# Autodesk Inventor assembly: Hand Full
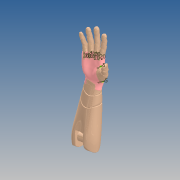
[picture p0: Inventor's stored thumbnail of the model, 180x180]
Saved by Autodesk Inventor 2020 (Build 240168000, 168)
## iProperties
Created: 2019-10
Part Number: Hand Full
Document SubType Name: Assembly
Designer: yello
Author: yello
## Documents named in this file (20)
- C:\Users\yello\Documents\Mechanical Hand\Prototype 2 (Realistic Hand)\Hand Full.iam
- C:\Users\yello\Documents\Mechanical Hand\Prototype 2 (Realistic Hand)\Palm.ipt
- C:\Users\yello\Documents\Mechanical Hand\Prototype 2 (Realistic Hand)\Wrist Rotation.ipt
- C:\Users\yello\Documents\Mechanical Hand\Prototype 2 (Realistic Hand)\Arm to Wrist Connection.ipt
- C:\Users\yello\Documents\Mechanical Hand\Prototype 2 (Realistic Hand)\Arm.ipt
- C:\Users\yello\Documents\Mechanical Hand\Prototype 2 (Realistic Hand)\Segment Thumb Finger Bottom.ipt
- C:\Users\yello\Documents\Mechanical Hand\Prototype 2 (Realistic Hand)\Segment Thumb Finger Middle.ipt
- C:\Users\yello\Documents\Mechanical Hand\Prototype 2 (Realistic Hand)\Segment Thumb Finger Top.ipt
- C:\Users\yello\Documents\Mechanical Hand\Prototype 2 (Realistic Hand)\Segment Index Finger Bottom.ipt
- C:\Users\yello\Documents\Mechanical Hand\Prototype 2 (Realistic Hand)\Segment Index Finger Middle.ipt
- C:\Users\yello\Documents\Mechanical Hand\Prototype 2 (Realistic Hand)\Segment Index Finger Top.ipt
- C:\Users\yello\Documents\Mechanical Hand\Prototype 2 (Realistic Hand)\Segment Middle Finger Bottom.ipt
- C:\Users\yello\Documents\Mechanical Hand\Prototype 2 (Realistic Hand)\Segment Middle Finger Middle.ipt
- C:\Users\yello\Documents\Mechanical Hand\Prototype 2 (Realistic Hand)\Segment Middle Finger Top.ipt
- C:\Users\yello\Documents\Mechanical Hand\Prototype 2 (Realistic Hand)\Segment Ring Finger Bottom.ipt
- C:\Users\yello\Documents\Mechanical Hand\Prototype 2 (Realistic Hand)\Segment Ring Finger Middle.ipt
- C:\Users\yello\Documents\Mechanical Hand\Prototype 2 (Realistic Hand)\Segment Ring Finger Top.ipt
- C:\Users\yello\Documents\Mechanical Hand\Prototype 2 (Realistic Hand)\Segment Pinkie Finger Bottom.ipt
- C:\Users\yello\Documents\Mechanical Hand\Prototype 2 (Realistic Hand)\Segment Pinkie Finger Middle.ipt
- C:\Users\yello\Documents\Mechanical Hand\Prototype 2 (Realistic Hand)\Segment Pinkie Finger Top.ipt
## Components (19 placed, 19 different names)
1. Palm:1 — Rotational:1, Rotational:2, Rotational:5, Rotational:8, Rotational:11, Rotational:14
2. Wrist Rotation:1 — Rotational:1, Mate:1, Mate:2, Mate:4
3. Arm to Wrist Connection:1 — Mate:1, Mate:2, Mate:3
4. Arm:1 — Mate:3, Mate:4
5. Segment Thumb Finger Bottom:1 — Rotational:2, Rotational:3
6. Segment Thumb Finger Middle:1 — Rotational:3, Rotational:4
7. Segment Thumb Finger Top:1 — Rotational:4
8. Segment Index Finger Bottom:1 — Rotational:5, Rotational:6
9. Segment Index Finger Middle:1 — Rotational:6, Rotational:7
10. Segment Index Finger Top:1 — Rotational:7
11. Segment Middle Finger Bottom:1 — Rotational:8, Rotational:9
12. Segment Middle Finger Middle:1 — Rotational:9, Rotational:10
13. Segment Middle Finger Top:1 — Rotational:10
14. Segment Ring Finger Bottom:1 — Rotational:11, Rotational:12
15. Segment Ring Finger Middle:1 — Rotational:12, Rotational:13
16. Segment Ring Finger Top:1 — Rotational:13
17. Segment Pinkie Finger Bottom:1 — Rotational:14, Rotational:15
18. Segment Pinkie Finger Middle:1 — Rotational:15, Rotational:16
19. Segment Pinkie Finger Top:1 — Rotational:16
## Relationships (20: RevoluteJoint 16, Mate 4)
- Rotational:1 [RevoluteJoint]: Palm:1 ↔ Wrist Rotation:1
- Mate:1: Wrist Rotation:1 ↔ Arm to Wrist Connection:1
- Mate:2: Wrist Rotation:1 ↔ Arm to Wrist Connection:1
- Mate:3: Arm to Wrist Connection:1 ↔ Arm:1
- Mate:4: Wrist Rotation:1 ↔ Arm:1
- Rotational:2 [RevoluteJoint]: Palm:1 ↔ Segment Thumb Finger Bottom:1
- Rotational:3 [RevoluteJoint]: Segment Thumb Finger Bottom:1 ↔ Segment Thumb Finger Middle:1
- Rotational:4 [RevoluteJoint]: Segment Thumb Finger Middle:1 ↔ Segment Thumb Finger Top:1
- Rotational:5 [RevoluteJoint]: Palm:1 ↔ Segment Index Finger Bottom:1
- Rotational:6 [RevoluteJoint]: Segment Index Finger Bottom:1 ↔ Segment Index Finger Middle:1
- Rotational:7 [RevoluteJoint]: Segment Index Finger Middle:1 ↔ Segment Index Finger Top:1
- Rotational:8 [RevoluteJoint]: Palm:1 ↔ Segment Middle Finger Bottom:1
- Rotational:9 [RevoluteJoint]: Segment Middle Finger Bottom:1 ↔ Segment Middle Finger Middle:1
- Rotational:10 [RevoluteJoint]: Segment Middle Finger Middle:1 ↔ Segment Middle Finger Top:1
- Rotational:11 [RevoluteJoint]: Palm:1 ↔ Segment Ring Finger Bottom:1
- Rotational:12 [RevoluteJoint]: Segment Ring Finger Bottom:1 ↔ Segment Ring Finger Middle:1
- Rotational:13 [RevoluteJoint]: Segment Ring Finger Middle:1 ↔ Segment Ring Finger Top:1
- Rotational:14 [RevoluteJoint]: Palm:1 ↔ Segment Pinkie Finger Bottom:1
- Rotational:15 [RevoluteJoint]: Segment Pinkie Finger Bottom:1 ↔ Segment Pinkie Finger Middle:1
- Rotational:16 [RevoluteJoint]: Segment Pinkie Finger Middle:1 ↔ Segment Pinkie Finger Top:1
